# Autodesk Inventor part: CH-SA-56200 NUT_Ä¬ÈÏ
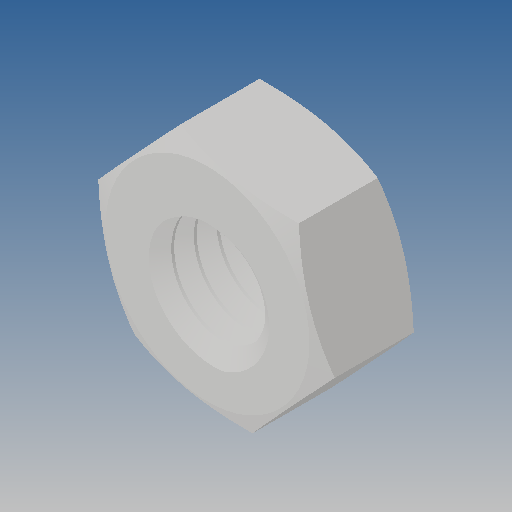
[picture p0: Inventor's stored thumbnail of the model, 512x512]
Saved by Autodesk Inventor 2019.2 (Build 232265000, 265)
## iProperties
Created: 2010-06
Part Number: CH-SA-56200 NUT_Ä¬ÈÏ
Material: Ogólny
Document SubType Name: Modeling
Designer: CADENGINEERING4
Density: 1 g/cm^3
Appearance: Domyślna
Author: CADENGINEERING4
Revision Number: ÈÎºÎ
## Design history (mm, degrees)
feature "NONE"
node "Bryła1"
